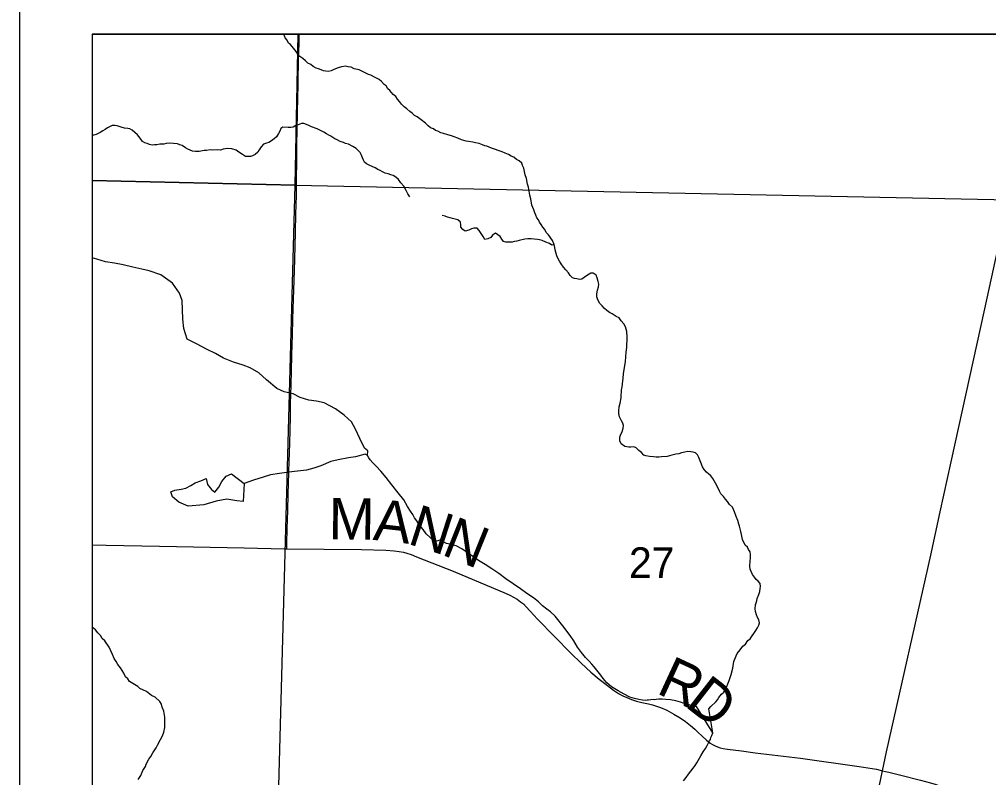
# Model space of a CAD drawing. Extents: x -8.8 to 41.4, y 0 to 34.6.
# Drawn here: x 2 to 3.33, y 19.88 to 20.92 of the extents above; entities that cross this region are included whole.
import ezdxf

# ---------------------------------------------------------------- set-up
doc = ezdxf.new("R2010")
doc.units = 0
for name, color, linetype in [('GM_X_Corporation', 7, 'Continuous'), ('GM_X_Minor_River', 7, 'Continuous'), ('GM_X_Section_Text', 7, 'Continuous'), ('GM_X_Township_Road', 7, 'Continuous'), ('GM_X_Township_Text', 7, 'Continuous'), ('GM_X_US_Route', 7, 'Continuous'), ('SH_Border', 7, 'Continuous')]:
    doc.layers.add(name, color=color, linetype=linetype)

msp = doc.modelspace()

# ---------------------------------------------------------------- linework, layer by layer
at = {"layer": 'GM_X_Corporation'}
for points in [[(2.3824, 20.9), (2.1, 20.9), (2.1, 20.6993), (2.3784, 20.6927)], [(3.3844, 20.9), (2.3824, 20.9), (2.3784, 20.6927), (3.381, 20.6722)], [(2.1, 20.6993), (2.1, 19.7037), (2.3512, 19.7001), (2.3784, 20.6927)], [(2.3784, 20.6927), (3.381, 20.6722), (3.3639, 19.6835), (2.3512, 19.7001)]]:
    msp.add_lwpolyline(points, close=True, dxfattribs=at)
msp.add_lwpolyline([(5.406, 20.9), (2.1, 20.9), (2.1, 18.6925)], dxfattribs=at)
at = {"layer": 'GM_X_Minor_River'}
for points in [[(2.6747, 20.7327), (2.671, 20.7347), (2.6665, 20.7368), (2.6624, 20.7385), (2.6477, 20.7435), (2.6443, 20.7448), (2.6414, 20.7464), (2.6383, 20.7469), (2.6353, 20.7482), (2.6305, 20.7499), (2.6255, 20.7508), (2.6222, 20.7517), (2.6161, 20.7526), (2.6127, 20.7531), (2.6067, 20.7549), (2.6014, 20.7573), (2.5966, 20.759), (2.5928, 20.7603), (2.5879, 20.7616), (2.5819, 20.7637), (2.5781, 20.7646), (2.574, 20.7667), (2.571, 20.7679), (2.568, 20.7699), (2.5639, 20.7712), (2.5606, 20.774), (2.5569, 20.7779), (2.551, 20.7823), (2.5458, 20.7863), (2.5421, 20.7884), (2.5388, 20.7915), (2.5354, 20.7939), (2.5314, 20.7975), (2.5277, 20.8003), (2.524, 20.8038), (2.5215, 20.8077), (2.5189, 20.8109), (2.5164, 20.8144), (2.5127, 20.8172), (2.5083, 20.8227), (2.5053, 20.8247), (2.5032, 20.8289), (2.5002, 20.8309), (2.4966, 20.8349), (2.4936, 20.8376), (2.488, 20.8405), (2.482, 20.8437), (2.4787, 20.8446), (2.4753, 20.8463), (2.4659, 20.8508), (2.4592, 20.8525), (2.455, 20.8546), (2.4509, 20.8551), (2.4479, 20.856), (2.4421, 20.855), (2.4371, 20.8537), (2.4314, 20.8512), (2.4275, 20.8495), (2.4237, 20.8488), (2.4206, 20.8489), (2.4172, 20.8498), (2.4139, 20.8511), (2.4101, 20.8523), (2.4071, 20.8532), (2.403, 20.8553), (2.3997, 20.8584), (2.3955, 20.8601), (2.3926, 20.8632), (2.3889, 20.8664), (2.3848, 20.8692), (2.3819, 20.8724), (2.3797, 20.8759), (2.3761, 20.8806), (2.3721, 20.8857), (2.3691, 20.8877), (2.3674, 20.8915), (2.3648, 20.8947), (2.3629, 20.9)], [(2.1546, 20.768), (2.1517, 20.77), (2.1486, 20.7705), (2.1441, 20.771), (2.1396, 20.7723), (2.1343, 20.7741), (2.1309, 20.7746), (2.1275, 20.7747), (2.1244, 20.7733), (2.1209, 20.7715), (2.1178, 20.7689), (2.1143, 20.7671), (2.1108, 20.765), (2.1054, 20.7621), (2.1019, 20.7615), (2.1, 20.7614)], [(2.5358, 20.6766), (2.533, 20.6809), (2.5305, 20.6856), (2.5272, 20.6914), (2.5232, 20.6961), (2.52, 20.7004), (2.5166, 20.7036), (2.5129, 20.706), (2.5095, 20.7069), (2.5058, 20.7082), (2.502, 20.709), (2.4983, 20.7111), (2.4949, 20.7127), (2.4915, 20.714), (2.4882, 20.7164), (2.4848, 20.718), (2.48, 20.7201), (2.4762, 20.7221), (2.4733, 20.7241), (2.4722, 20.7272), (2.4708, 20.7303), (2.4687, 20.7346), (2.4673, 20.7377), (2.4621, 20.7428), (2.4573, 20.7456), (2.4513, 20.7489), (2.4475, 20.7498), (2.4446, 20.7514), (2.44, 20.7527), (2.4359, 20.7551), (2.4326, 20.7564), (2.4274, 20.76), (2.4244, 20.7612), (2.4214, 20.7633), (2.4177, 20.7653), (2.4087, 20.7698), (2.4008, 20.7727), (2.3971, 20.7744), (2.3937, 20.776), (2.3903, 20.7773), (2.3869, 20.7774), (2.3823, 20.7757), (2.3792, 20.7746), (2.3757, 20.7725), (2.3723, 20.7718), (2.3685, 20.772), (2.3616, 20.7722), (2.3585, 20.7704), (2.3573, 20.767), (2.3556, 20.7637), (2.3528, 20.7592), (2.3497, 20.7562), (2.3458, 20.7537), (2.3423, 20.7512), (2.3388, 20.7502), (2.335, 20.7488), (2.3318, 20.7451), (2.329, 20.7414), (2.327, 20.738), (2.3234, 20.7347), (2.3199, 20.7329), (2.3169, 20.7319), (2.3104, 20.7321), (2.3059, 20.7349), (2.3011, 20.7382), (2.2974, 20.7409), (2.2914, 20.7427), (2.2861, 20.7429), (2.2826, 20.7426), (2.2796, 20.7419), (2.2757, 20.7409), (2.2719, 20.7411), (2.2655, 20.7409), (2.2617, 20.7411), (2.2567, 20.7401), (2.2533, 20.7402), (2.2464, 20.7389), (2.2418, 20.7387), (2.2377, 20.7392), (2.2343, 20.7409), (2.2309, 20.7421), (2.2279, 20.7441), (2.2231, 20.747), (2.2201, 20.7482), (2.2167, 20.7495), (2.2114, 20.75), (2.2065, 20.7502), (2.2015, 20.75), (2.1981, 20.749), (2.1927, 20.7488), (2.1885, 20.7482), (2.1855, 20.7479), (2.1821, 20.7476), (2.1783, 20.7485), (2.1753, 20.7498), (2.1723, 20.7506), (2.1689, 20.7527), (2.1657, 20.7574), (2.162, 20.7617), (2.1583, 20.7652), (2.1546, 20.768)], [(2.8462, 20.3324), (2.8428, 20.3336), (2.839, 20.3334), (2.8359, 20.3335), (2.8306, 20.3344), (2.8254, 20.3377), (2.8237, 20.3419), (2.8239, 20.3472), (2.8251, 20.351), (2.8268, 20.3544), (2.8281, 20.3593), (2.8286, 20.363), (2.828, 20.3661), (2.8262, 20.3696), (2.8233, 20.375), (2.8223, 20.3793), (2.8221, 20.3831), (2.823, 20.3887), (2.824, 20.3937), (2.8254, 20.4008), (2.8255, 20.405), (2.826, 20.4088), (2.8261, 20.4118), (2.8267, 20.4156), (2.8277, 20.4244), (2.8282, 20.4274), (2.8288, 20.4342), (2.8307, 20.4448), (2.8313, 20.4509), (2.8319, 20.4573), (2.8325, 20.4638), (2.8331, 20.4702), (2.8336, 20.4843), (2.8332, 20.4919), (2.8315, 20.4984), (2.829, 20.5027), (2.8257, 20.5066), (2.8228, 20.5105), (2.8187, 20.5126), (2.8131, 20.5162), (2.8094, 20.5182), (2.806, 20.521), (2.8027, 20.5234), (2.7994, 20.5273), (2.7961, 20.5305), (2.7936, 20.5352), (2.7922, 20.5394), (2.792, 20.5436), (2.7929, 20.5485), (2.7943, 20.5534), (2.7948, 20.5568), (2.7941, 20.5607), (2.7928, 20.5656), (2.791, 20.5691), (2.7869, 20.5719), (2.7839, 20.572), (2.7792, 20.5692), (2.7749, 20.5659), (2.7714, 20.5637), (2.7684, 20.5635), (2.7646, 20.564), (2.7616, 20.5645), (2.7586, 20.5657), (2.7556, 20.5688), (2.7535, 20.5723), (2.7494, 20.5767), (2.7465, 20.5802), (2.7433, 20.5849), (2.7407, 20.5884), (2.7393, 20.5915), (2.7372, 20.5958), (2.7362, 20.5988), (2.7352, 20.6042), (2.7346, 20.6073), (2.7336, 20.6115), (2.7315, 20.6169), (2.7257, 20.6247), (2.7227, 20.6279), (2.7206, 20.6317), (2.718, 20.6349), (2.7159, 20.6388), (2.7137, 20.6419), (2.7119, 20.645), (2.7098, 20.6481), (2.7084, 20.6516), (2.7069, 20.6547), (2.7056, 20.6589), (2.7031, 20.6651), (2.7015, 20.6739), (2.7002, 20.6789), (2.6983, 20.69), (2.6969, 20.6942), (2.6957, 20.7019), (2.694, 20.7069), (2.692, 20.7161), (2.6902, 20.7196), (2.6892, 20.7231), (2.6855, 20.7262), (2.6818, 20.7279), (2.6781, 20.7311), (2.6747, 20.7327)], [(2.7336, 20.6115), (2.7305, 20.6105), (2.7271, 20.6125), (2.7223, 20.6146), (2.717, 20.6166), (2.7136, 20.6175), (2.7106, 20.618), (2.7064, 20.6185), (2.7019, 20.6191), (2.6973, 20.6189), (2.6935, 20.6186), (2.6858, 20.6166), (2.6824, 20.6159), (2.6793, 20.6153), (2.6759, 20.6147), (2.6717, 20.6144), (2.6671, 20.6146), (2.6641, 20.6154), (2.6616, 20.6186), (2.6594, 20.6221), (2.6564, 20.6245), (2.6531, 20.6269), (2.6492, 20.6243), (2.6468, 20.621), (2.6426, 20.6192), (2.6387, 20.6182), (2.6362, 20.6225), (2.6333, 20.6264), (2.6308, 20.6303), (2.6279, 20.6335), (2.6233, 20.6336), (2.6202, 20.633), (2.6164, 20.6308), (2.6114, 20.6295), (2.6084, 20.6319), (2.6055, 20.635), (2.6056, 20.6384), (2.6053, 20.6419), (2.6013, 20.645), (2.5979, 20.6459), (2.5941, 20.6468), (2.5911, 20.6477), (2.5873, 20.6486), (2.584, 20.6502), (2.5798, 20.6511)], [(2.4778, 20.3281), (2.4732, 20.3321), (2.4672, 20.3452), (2.4612, 20.3579), (2.4554, 20.368), (2.4454, 20.3774), (2.4336, 20.3858), (2.4183, 20.3943), (2.4077, 20.3965), (2.3971, 20.3976), (2.3851, 20.4014), (2.3754, 20.4066), (2.3634, 20.4093), (2.3533, 20.4138), (2.3392, 20.4256), (2.3285, 20.4351), (2.3166, 20.4419), (2.3069, 20.446), (2.2937, 20.4498), (2.2802, 20.4552), (2.269, 20.4616), (2.2578, 20.4673), (2.2429, 20.475), (2.2302, 20.4815), (2.2257, 20.4961), (2.2242, 20.5087), (2.2239, 20.522), (2.2231, 20.5345), (2.2196, 20.5445), (2.2102, 20.5582), (2.1942, 20.5697), (2.1781, 20.5751), (2.1679, 20.5773), (2.1555, 20.58), (2.1423, 20.5835), (2.1303, 20.5857), (2.1182, 20.5876), (2.1062, 20.5914), (2.1, 20.5929)], [(2.9513, 19.9414), (2.9457, 19.9743), (2.9485, 19.9777), (2.9552, 19.9839), (2.9575, 19.9868), (2.9596, 19.9898), (2.9631, 19.9943), (2.9663, 19.9972), (2.9679, 20.0006), (2.9704, 20.005), (2.972, 20.0088), (2.9737, 20.0133), (2.9762, 20.0212), (2.9785, 20.0299), (2.9793, 20.0332), (2.9803, 20.0393), (2.9832, 20.0472), (2.9845, 20.0502), (2.9889, 20.0554), (2.9925, 20.0602), (2.996, 20.0631), (2.9992, 20.0679), (3.0023, 20.0705), (3.0103, 20.0816), (3.0127, 20.0853), (3.0144, 20.0891), (3.0153, 20.0921), (3.0143, 20.0963), (3.0125, 20.0998), (3.0111, 20.1033), (3.0097, 20.1079), (3.0095, 20.1117), (3.01, 20.117), (3.0114, 20.1223), (3.0123, 20.1257), (3.0144, 20.1313), (3.0156, 20.1354), (3.0162, 20.1392), (3.0166, 20.1423), (3.0164, 20.1461), (3.0135, 20.1496), (3.0105, 20.1516), (3.0083, 20.1547), (3.0058, 20.1586), (3.0037, 20.1629), (3.0023, 20.166), (3.002, 20.1702), (3.0023, 20.1774), (3.0028, 20.1808), (3.003, 20.1861), (3.0023, 20.1895), (3.0002, 20.1927), (2.9988, 20.1961), (2.9958, 20.1989), (2.9919, 20.2067), (2.9906, 20.2135), (2.9896, 20.2174), (2.988, 20.2247), (2.987, 20.2278), (2.9856, 20.2327), (2.9835, 20.2381), (2.9811, 20.2447), (2.9783, 20.2509), (2.9742, 20.2548), (2.9713, 20.2587), (2.9688, 20.2619), (2.9659, 20.2654), (2.9622, 20.2693), (2.9604, 20.2728), (2.9579, 20.2779), (2.9551, 20.2837), (2.9533, 20.2871), (2.9511, 20.2903), (2.9486, 20.2938), (2.9456, 20.2962), (2.9427, 20.2989), (2.9394, 20.3025), (2.9369, 20.3064), (2.9348, 20.3121), (2.932, 20.3191), (2.9302, 20.3226), (2.9273, 20.3257), (2.9243, 20.3266), (2.9213, 20.3271), (2.9171, 20.3272), (2.9129, 20.3266), (2.9083, 20.3253), (2.9048, 20.3242), (2.9006, 20.3236), (2.8952, 20.3223), (2.8887, 20.3206), (2.8807, 20.3201), (2.8773, 20.3195), (2.8735, 20.3196), (2.8697, 20.3201), (2.8644, 20.3207), (2.8595, 20.3213), (2.8565, 20.3225), (2.8532, 20.326), (2.8498, 20.3288), (2.8462, 20.3324)], [(2.4776, 20.3217), (2.4745, 20.3237), (2.4611, 20.3199), (2.4516, 20.3187), (2.4371, 20.3161), (2.4272, 20.3134), (2.4133, 20.3077), (2.4038, 20.3046), (2.3938, 20.3018), (2.3816, 20.3003), (2.3698, 20.2992), (2.3569, 20.2973), (2.3447, 20.2954), (2.3343, 20.2923), (2.3213, 20.2881), (2.3083, 20.2836)], [(2.503, 20.2917), (2.4957, 20.3004), (2.4895, 20.3071), (2.4848, 20.3119), (2.4811, 20.3158), (2.4793, 20.3186), (2.4776, 20.3217), (2.4778, 20.3281)], [(2.2078, 20.2719), (2.2132, 20.2743), (2.2219, 20.2756), (2.2284, 20.2769), (2.2354, 20.2809), (2.2412, 20.2845), (2.2489, 20.2873), (2.2561, 20.2901), (2.2582, 20.2821), (2.2637, 20.2754), (2.2681, 20.2715), (2.2736, 20.2782), (2.2776, 20.286), (2.2836, 20.2935), (2.2912, 20.2966), (2.3083, 20.2836)], [(2.911, 19.8757), (2.9146, 19.8801), (2.9178, 19.8846), (2.9242, 19.8927), (2.927, 19.8964), (2.9294, 19.9001), (2.9348, 19.9098), (2.938, 19.9153), (2.9413, 19.9201), (2.9437, 19.9242), (2.9454, 19.9276), (2.9466, 19.9302), (2.9482, 19.9324), (2.9487, 19.9351), (2.95, 19.9377), (2.9513, 19.9414), (2.9288, 19.9777), (2.9257, 19.9771), (2.9219, 19.978), (2.9186, 19.9796), (2.9152, 19.9809), (2.9118, 19.9818), (2.9069, 19.9835), (2.9005, 19.9853), (2.8934, 19.9867), (2.8869, 19.9873), (2.8816, 19.9876), (2.8771, 19.9874), (2.8736, 19.9871), (2.8713, 19.9868), (2.8694, 19.9869), (2.866, 19.9867), (2.8629, 19.9864), (2.861, 19.9861), (2.8584, 19.9858), (2.8546, 19.9863), (2.8497, 19.9869), (2.844, 19.9883), (2.8373, 19.9905), (2.8298, 19.9942), (2.8213, 19.9991), (2.8123, 20.0044), (2.8057, 20.01), (2.801, 20.0159), (2.7974, 20.0206), (2.7941, 20.0249), (2.7884, 20.032), (2.7855, 20.0355), (2.7814, 20.0395), (2.7767, 20.0446), (2.7713, 20.0517), (2.7655, 20.0591), (2.7605, 20.0677), (2.7555, 20.0751), (2.7512, 20.081), (2.7472, 20.0857), (2.7349, 20.1014), (2.7286, 20.1074), (2.7235, 20.111), (2.7176, 20.1158), (2.7121, 20.1213), (2.7051, 20.1266), (2.6962, 20.1326), (2.6873, 20.1391), (2.6674, 20.1528), (2.6578, 20.16), (2.6481, 20.1665), (2.6389, 20.1722), (2.63, 20.1779), (2.6222, 20.1831), (2.6144, 20.1888), (2.607, 20.1936), (2.5992, 20.1977), (2.5921, 20.1999), (2.5857, 20.2013), (2.5804, 20.2038), (2.5763, 20.2055), (2.574, 20.2048), (2.5717, 20.2045), (2.5691, 20.2054), (2.5661, 20.2067), (2.5635, 20.2094), (2.558, 20.2146), (2.5537, 20.2205), (2.549, 20.2264), (2.5451, 20.2322), (2.5418, 20.2365), (2.5397, 20.2408), (2.5365, 20.2455), (2.5326, 20.2521), (2.5272, 20.2611), (2.5196, 20.2705), (2.5109, 20.2815), (2.503, 20.2917)], [(2.3083, 20.2836), (2.3071, 20.2589), (2.2984, 20.2595), (2.2845, 20.2619), (2.27, 20.2593), (2.2531, 20.2541), (2.2315, 20.2525), (2.2187, 20.2578), (2.2099, 20.2653), (2.2078, 20.2719)], [(2.1112, 20.0751), (2.1075, 20.0786), (2.1042, 20.0825), (2.1, 20.0863)], [(2.1631, 19.8774), (2.1664, 19.883), (2.1693, 19.8897), (2.1729, 19.8953), (2.1741, 19.8983), (2.1774, 19.9054), (2.1802, 19.9091), (2.1831, 19.9139), (2.1875, 19.921), (2.1895, 19.9244), (2.1936, 19.9322), (2.1964, 19.9374), (2.1981, 19.9423), (2.1995, 19.9487), (2.1996, 19.9529), (2.1996, 19.9628), (2.1987, 19.9682), (2.198, 19.9712), (2.1959, 19.9766), (2.1949, 19.9805), (2.1928, 19.9843), (2.1861, 19.9903), (2.1813, 19.9927), (2.1742, 19.9979), (2.1701, 20), (2.1653, 20.0024), (2.1623, 20.0048), (2.1578, 20.0076), (2.1512, 20.012), (2.1486, 20.0156), (2.1457, 20.0183), (2.1432, 20.0234), (2.1385, 20.0304), (2.1352, 20.035), (2.1327, 20.0393), (2.1298, 20.0432), (2.1277, 20.049), (2.1231, 20.0587), (2.117, 20.0676), (2.1137, 20.0708), (2.1112, 20.0751)]]:
    msp.add_lwpolyline(points, dxfattribs=at)
at = {"layer": 'GM_X_Township_Road'}
for points in [[(2.3667, 20.1938), (2.3669, 20.2005), (2.367, 20.2036), (2.368, 20.2359), (2.3682, 20.244), (2.3689, 20.2712), (2.3692, 20.2818), (2.3697, 20.3004), (2.3708, 20.3389), (2.3713, 20.3569), (2.3717, 20.3743), (2.3717, 20.3811), (2.372, 20.3941), (2.3723, 20.4046), (2.3729, 20.4195), (2.3733, 20.4369), (2.3739, 20.4605), (2.3746, 20.4872), (2.3752, 20.5082), (2.3755, 20.5231), (2.3763, 20.5492), (2.3768, 20.5616), (2.3778, 20.5914), (2.3787, 20.6281), (2.3794, 20.6529), (2.38, 20.6784), (2.3803, 20.6964), (2.3804, 20.7306), (2.3807, 20.7517), (2.381, 20.766), (2.3816, 20.7946), (2.382, 20.8107), (2.3824, 20.8318), (2.3826, 20.8436), (2.3828, 20.8554), (2.3831, 20.8672), (2.3836, 20.8864), (2.3839, 20.9)], [(2.1, 20.1995), (2.119, 20.199), (2.1922, 20.1974), (2.3084, 20.195), (2.3637, 20.1938), (2.3667, 20.1938), (2.4693, 20.1928), (2.5028, 20.1918), (2.5139, 20.1909), (2.5212, 20.19), (2.5267, 20.189), (2.5314, 20.1878), (2.5373, 20.1859), (2.5448, 20.183), (2.595, 20.1631), (2.6676, 20.1323), (2.6728, 20.1302), (2.6779, 20.1277), (2.683, 20.1247), (2.6876, 20.1213), (2.6914, 20.1182), (2.6953, 20.1144), (2.7007, 20.1084), (2.7109, 20.0974), (2.7341, 20.0734), (2.7563, 20.0507), (2.7707, 20.037), (2.7841, 20.0248), (2.7954, 20.0151), (2.8066, 20.0062), (2.8151, 19.9999), (2.822, 19.9955), (2.828, 19.9922), (2.8332, 19.9898), (2.8396, 19.9873), (2.8467, 19.985), (2.854, 19.9832), (2.8631, 19.9812), (2.8685, 19.9799), (2.8755, 19.9777), (2.8796, 19.9762), (2.888, 19.9724), (2.8978, 19.9672), (2.9063, 19.962), (2.9139, 19.9568), (2.9208, 19.9515), (2.9268, 19.9463), (2.9312, 19.9419), (2.9361, 19.9371), (2.9424, 19.9311), (2.9475, 19.9273), (2.9507, 19.9253), (2.9553, 19.923), (2.9612, 19.9209), (2.9653, 19.9197), (2.9716, 19.9188), (2.9907, 19.9165), (3.0092, 19.9141), (3.0715, 19.9066), (3.1522, 19.8951), (3.1756, 19.8913), (3.1842, 19.8894)], [(3.1842, 19.8894), (3.1882, 19.8885), (3.1926, 19.8875), (3.2108, 19.883), (3.2361, 19.8765), (3.2499, 19.8727), (3.2575, 19.8703), (3.2639, 19.8679), (3.2697, 19.8655), (3.2758, 19.8625), (3.2857, 19.8572), (3.3113, 19.8421), (3.3298, 19.8319)]]:
    msp.add_lwpolyline(points, dxfattribs=at)
at = {"layer": 'GM_X_US_Route'}
msp.add_lwpolyline([(3.1416, 18.7742), (3.1431, 18.8767), (3.1445, 18.9798), (3.1478, 19.1979), (3.1501, 19.3538), (3.1524, 19.5036), (3.1544, 19.6409), (3.1555, 19.6825), (3.1563, 19.6999), (3.1578, 19.7229), (3.1597, 19.7446), (3.1621, 19.7656), (3.1645, 19.7841), (3.1669, 19.8001), (3.1715, 19.8277), (3.1754, 19.8478), (3.1818, 19.8782), (3.1842, 19.8894), (3.1896, 19.9152), (3.2502, 20.1851), (3.2632, 20.2446), (3.2783, 20.3131), (3.3245, 20.5232), (3.3482, 20.6317)], dxfattribs=at)
at = {"layer": 'SH_Border'}
for p, q in [((2, 21), (2, 14)), ((2.1, 20.9), (2.1, 14.1)), ((2.1, 20.9), (8.9, 20.9))]:
    msp.add_line(p, q, dxfattribs=at)

# ---------------------------------------------------------------- texts
at = {"layer": 'GM_X_Section_Text'}
for s, rotation, p in [('M', 359.2852, (2.4239, 20.2069)), ('A', 353.6376, (2.4841, 20.2062)), ('N', 342.1891, (2.5309, 20.2013)), ('N', 338.1181, (2.5775, 20.1864)), ('R', 335.1549, (2.8723, 19.9964)), ('D', 322.0997, (2.9117, 19.9786))]:
    msp.add_text(s, height=0.0568, rotation=rotation, dxfattribs=at).set_placement(p)
at = {"layer": 'GM_X_Township_Text'}
msp.add_text('27', height=0.04186, rotation=0, dxfattribs=at).set_placement((2.8363, 20.154))

doc.saveas('drawing.dxf')
